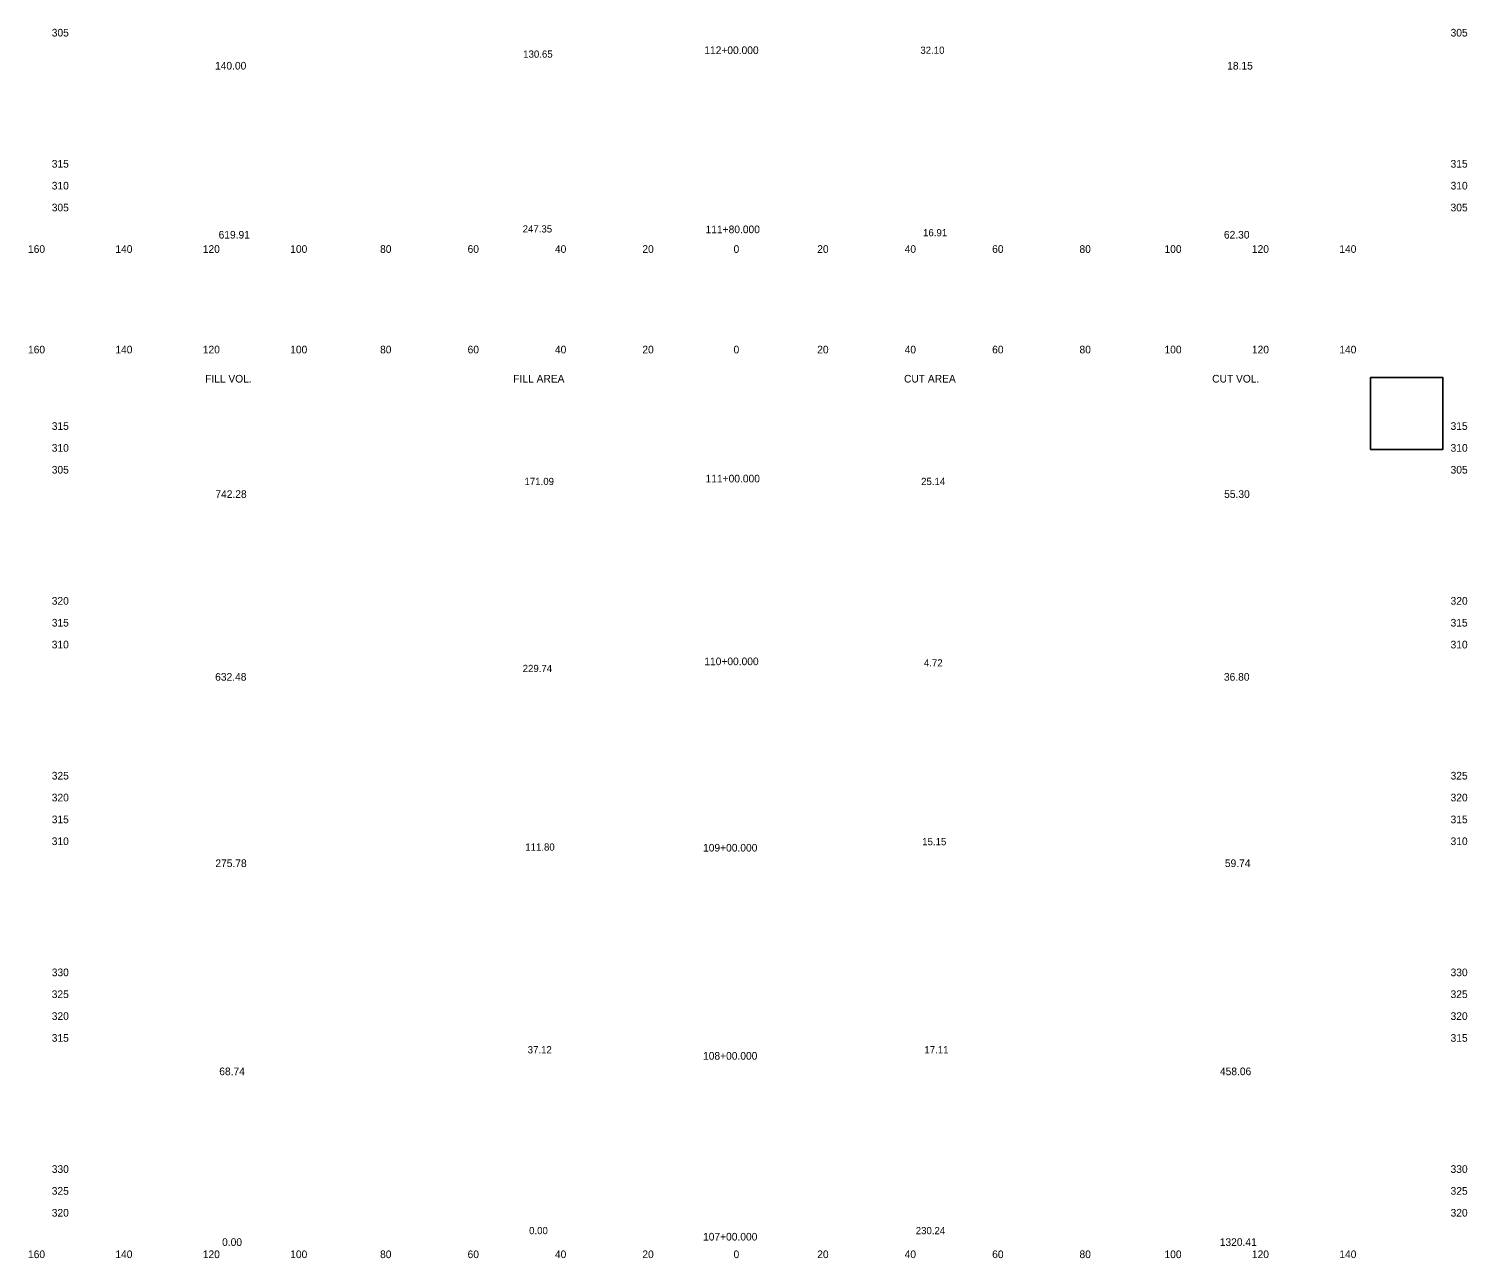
# Model space of a CAD drawing. Extents: x 21477 to 21806, y 6470 to 11049.
# Drawn here: x 21477.1 to 21806.1, y 7620.3 to 7901.6 of the extents above; entities that cross this region are included whole.
import ezdxf

# ---------------------------------------------------------------- set-up
doc = ezdxf.new("R2010")
doc.units = 0
for name, color, linetype in [('SHEET_CONSULTANT_STAMP', 7, 'Continuous'), ('XS_SHEET_EW_TX_AREA', 7, 'Continuous'), ('XS_SHEET_EW_TX_VOLUME', 7, 'Continuous'), ('XS_SHEET_LABELS_ELEVATION', 7, 'Continuous'), ('XS_SHEET_LABELS_OFFSET', 7, 'Continuous'), ('XS_SHEET_LABELS_STATION', 7, 'Continuous'), ('XS_SHEET_TX', 7, 'Continuous')]:
    doc.layers.add(name, color=color, linetype=linetype)

msp = doc.modelspace()

# ---------------------------------------------------------------- linework, layer by layer
at = {"layer": 'SHEET_CONSULTANT_STAMP'}
msp.add_lwpolyline([(21784.04, 7805.34), (21800.54, 7805.34), (21800.54, 7821.84), (21784.04, 7821.84)], close=True, dxfattribs=at)

# ---------------------------------------------------------------- texts
at = {"layer": 'XS_SHEET_EW_TX_AREA'}
for s, p in [(' 130.65 ', (21589.57, 7894.99)), (' 32.10 ', (21680.43, 7895.88)), (' 247.35 ', (21589.45, 7855)), (' 16.91 ', (21681.05, 7854.14)), (' 171.09 ', (21589.87, 7797.22)), (' 25.14 ', (21680.6, 7797.22)), (' 4.72 ', (21681.24, 7755.71)), (' 229.74 ', (21589.45, 7754.43)), (' 111.80 ', (21590.04, 7713.57)), (' 15.15 ', (21680.85, 7714.81)), (' 37.12 ', (21590.6, 7667.19)), (' 17.11 ', (21681.35, 7667.19)), (' 0.00 ', (21590.92, 7625.81)), (' 230.24 ', (21679.37, 7625.81))]:
    msp.add_text(s, height=1.65, dxfattribs=at).set_placement(p)
at = {"layer": 'XS_SHEET_EW_TX_VOLUME'}
for s, p in [(' 140.00 ', (21519.04, 7892.28)), (' 18.15 ', (21750.59, 7892.28)), (' 619.91 ', (21519.86, 7853.61)), (' 62.30 ', (21749.84, 7853.61)), (' 742.28 ', (21519.12, 7794.27)), (' 55.30 ', (21749.89, 7794.27)), (' 632.48 ', (21519.07, 7752.45)), (' 36.80 ', (21749.84, 7752.45)), (' 275.78 ', (21519.12, 7709.81)), (' 59.74 ', (21750.06, 7709.81)), (' 68.74 ', (21520.01, 7662.19)), (' 458.06 ', (21748.93, 7662.19)), (' 0.00 ', (21520.66, 7623.13)), (' 1320.41 ', (21748.89, 7623.13))]:
    msp.add_text(s, height=1.75, dxfattribs=at).set_placement(p)
at = {"layer": 'XS_SHEET_LABELS_ELEVATION'}
for s, p in [('  305  ', (21481.04, 7899.84)), ('  305  ', (21801.04, 7899.84)), ('  315  ', (21481.04, 7869.84)), ('  315  ', (21801.04, 7869.84)), ('  310  ', (21481.04, 7864.84)), ('  310  ', (21801.04, 7864.84)), ('  305  ', (21481.04, 7859.84)), ('  305  ', (21801.04, 7859.84)), ('  315  ', (21481.04, 7809.84)), ('  315  ', (21801.04, 7809.84)), ('  310  ', (21481.04, 7804.84)), ('  310  ', (21801.04, 7804.84)), ('  305  ', (21481.04, 7799.84)), ('  305  ', (21801.04, 7799.84)), ('  320  ', (21481.04, 7769.84)), ('  320  ', (21801.04, 7769.84)), ('  315  ', (21481.04, 7764.84)), ('  315  ', (21801.04, 7764.84)), ('  310  ', (21481.04, 7759.84)), ('  310  ', (21801.04, 7759.84)), ('  325  ', (21481.04, 7729.84)), ('  325  ', (21801.04, 7729.84)), ('  320  ', (21481.04, 7724.84)), ('  320  ', (21801.04, 7724.84)), ('  315  ', (21481.04, 7719.84)), ('  315  ', (21801.04, 7719.84)), ('  310  ', (21481.04, 7714.84)), ('  310  ', (21801.04, 7714.84)), ('  330  ', (21481.04, 7684.84)), ('  330  ', (21801.04, 7684.84)), ('  325  ', (21481.04, 7679.84)), ('  325  ', (21801.04, 7679.84)), ('  320  ', (21481.04, 7674.84)), ('  320  ', (21801.04, 7674.84)), ('  315  ', (21481.04, 7669.84)), ('  315  ', (21801.04, 7669.84)), ('  330  ', (21481.04, 7639.84)), ('  330  ', (21801.04, 7639.84)), ('  325  ', (21481.04, 7634.84)), ('  325  ', (21801.04, 7634.84)), ('  320  ', (21481.04, 7629.84)), ('  320  ', (21801.04, 7629.84))]:
    msp.add_text(s, height=1.75, dxfattribs=at).set_placement(p)
at = {"layer": 'XS_SHEET_LABELS_OFFSET'}
for s, p in [('  160  ', (21475.6, 7850.34)), ('  140  ', (21495.59, 7850.34)), ('  120  ', (21515.59, 7850.34)), ('  100  ', (21535.59, 7850.34)), ('  80  ', (21556.15, 7850.34)), ('  60  ', (21576.17, 7850.34)), ('  40  ', (21596.15, 7850.34)), ('  20  ', (21616.15, 7850.34)), ('  0  ', (21637.01, 7850.34)), ('  0  ', (21637.01, 7850.34)), ('  20  ', (21656.15, 7850.34)), ('  40  ', (21676.15, 7850.34)), ('  60  ', (21696.17, 7850.34)), ('  80  ', (21716.15, 7850.34)), ('  100  ', (21735.59, 7850.34)), ('  120  ', (21755.59, 7850.34)), ('  140  ', (21775.59, 7850.34)), ('  160  ', (21475.6, 7827.34)), ('  140  ', (21495.59, 7827.34)), ('  120  ', (21515.59, 7827.34)), ('  100  ', (21535.59, 7827.34)), ('  80  ', (21556.15, 7827.34)), ('  60  ', (21576.17, 7827.34)), ('  40  ', (21596.15, 7827.34)), ('  20  ', (21616.15, 7827.34)), ('  0  ', (21637.01, 7827.34)), ('  0  ', (21637.01, 7827.34)), ('  20  ', (21656.15, 7827.34)), ('  40  ', (21676.15, 7827.34)), ('  60  ', (21696.17, 7827.34)), ('  80  ', (21716.15, 7827.34)), ('  100  ', (21735.59, 7827.34)), ('  120  ', (21755.59, 7827.34)), ('  140  ', (21775.59, 7827.34)), ('  160  ', (21475.6, 7620.34)), ('  140  ', (21495.59, 7620.34)), ('  120  ', (21515.59, 7620.34)), ('  100  ', (21535.59, 7620.34)), ('  80  ', (21556.15, 7620.34)), ('  60  ', (21576.17, 7620.34)), ('  40  ', (21596.15, 7620.34)), ('  20  ', (21616.15, 7620.34)), ('  0  ', (21637.01, 7620.34)), ('  0  ', (21637.01, 7620.34)), ('  20  ', (21656.15, 7620.34)), ('  40  ', (21676.15, 7620.34)), ('  60  ', (21696.17, 7620.34)), ('  80  ', (21716.15, 7620.34)), ('  100  ', (21735.59, 7620.34)), ('  120  ', (21755.59, 7620.34)), ('  140  ', (21775.59, 7620.34))]:
    msp.add_text(s, height=1.75, dxfattribs=at).set_placement(p)
at = {"layer": 'XS_SHEET_LABELS_STATION'}
for s, p in [('  112+00.000  ', (21630.32, 7895.83)), ('  111+80.000  ', (21630.61, 7854.84)), ('  111+00.000  ', (21630.61, 7797.82)), ('  110+00.000  ', (21630.32, 7756)), ('  109+00.000  ', (21630.03, 7713.36)), ('  108+00.000  ', (21630.03, 7665.74)), ('  107+00.000  ', (21630.03, 7624.36))]:
    msp.add_text(s, height=1.75, dxfattribs=at).set_placement(p)
at = {"layer": 'XS_SHEET_TX'}
for s, p in [('FILL VOL.', (21517.41, 7820.67)), ('FILL AREA', (21587.92, 7820.67)), ('CUT AREA', (21677.31, 7820.67)), ('CUT VOL.', (21747.8, 7820.67))]:
    msp.add_text(s, height=1.75, dxfattribs=at).set_placement(p)

doc.saveas('drawing.dxf')
